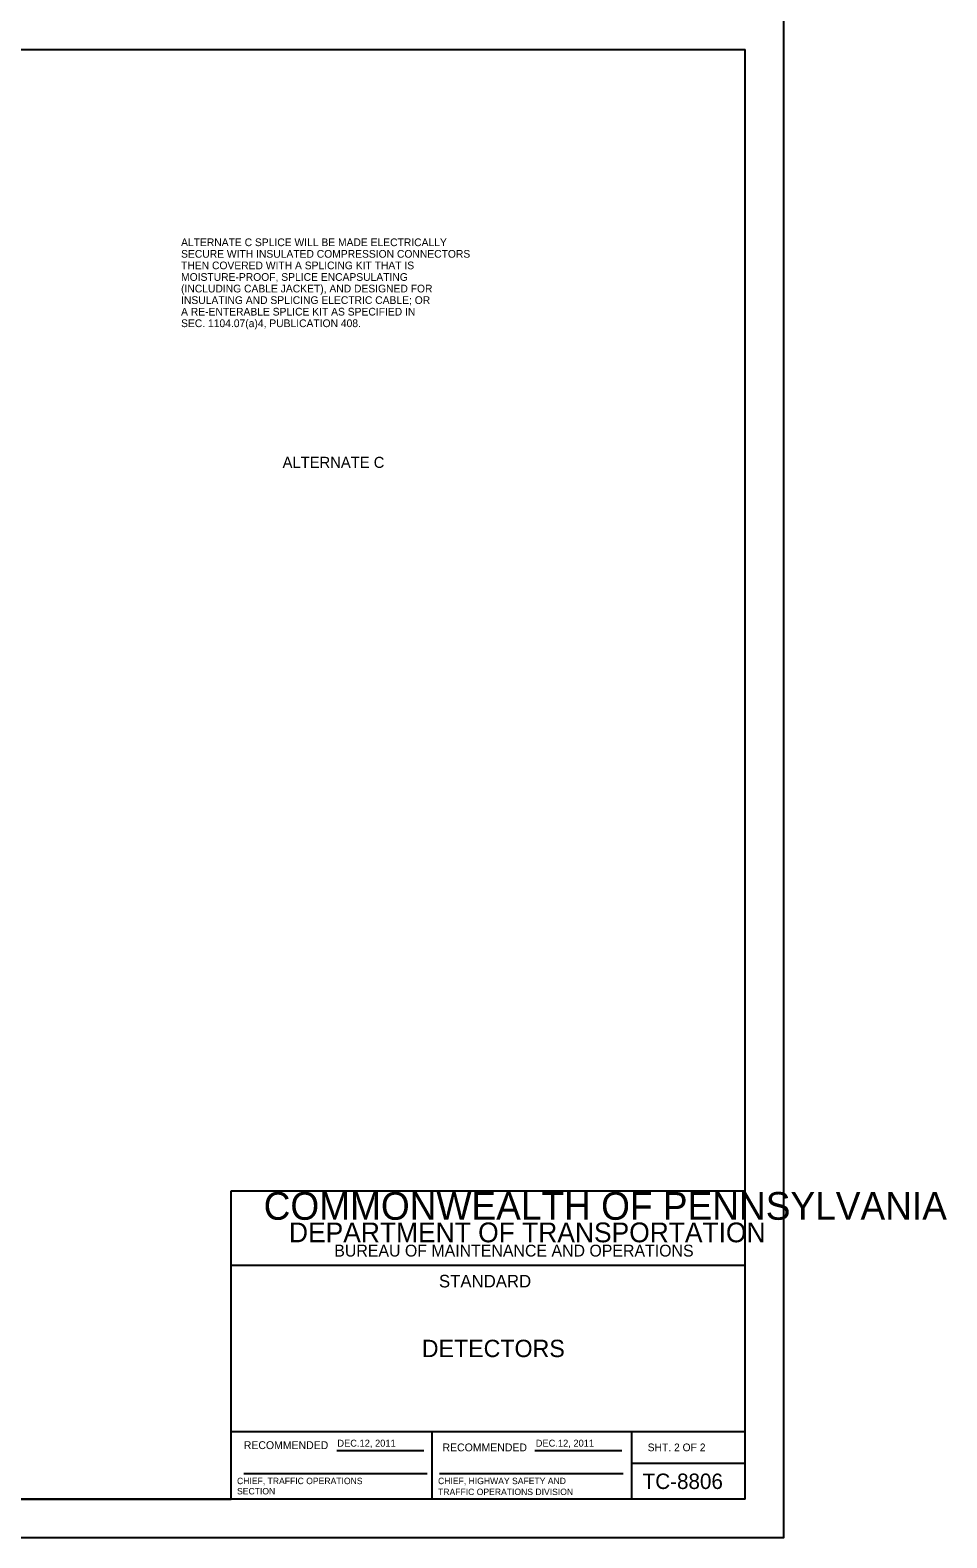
# Model space of a CAD drawing. Extents: x 2709 to 3899, y 22 to 1210.
# Drawn here: x 3257 to 3613, y 22 to 609 of the extents above; entities that cross this region are included whole.
import ezdxf

# ---------------------------------------------------------------- set-up
doc = ezdxf.new("R2010")
doc.units = 0
for name, color, linetype in [('1', 7, 'Continuous'), ('2', 7, 'Continuous'), ('4', 7, 'Continuous'), ('Default', 7, 'Continuous'), ('PLT-BNDY', 7, 'Continuous')]:
    doc.layers.add(name, color=color, linetype=linetype)

msp = doc.modelspace()

# ---------------------------------------------------------------- linework, layer by layer
at = {"layer": '1'}
for p, q in [((2748.86, 601.17), (3534.86, 601.17)), ((3534.86, 37.17), (3534.86, 601.17)), ((3334.86, 37.17), (3334.86, 157.17)), ((3334.86, 157.17), (3534.86, 157.17)), ((3534.86, 128.17), (3334.86, 128.17)), ((3334.86, 63.55), (3534.86, 63.55)), ((3412.86, 63.55), (3412.86, 37.17)), ((3490.73, 37.17), (3490.73, 63.55)), ((3375.9, 56.2), (3409.82, 56.2)), ((3452.99, 56.2), (3486.91, 56.2)), ((3339.74, 47.21), (3411.07, 47.21)), ((3415.95, 47.21), (3487.41, 47.21)), ((3490.73, 51.17), (3534.86, 51.17)), ((3534.86, 37.17), (2748.86, 37.17)), ((2748.86, 37.17), (3334.86, 37.17))]:
    msp.add_line(p, q, dxfattribs=at)
at = {"layer": 'PLT-BNDY'}
msp.add_lwpolyline([(2708.86, 616.17), (3549.86, 616.17), (3549.86, 22.17), (2708.86, 22.17)], close=True, dxfattribs=at)

# ---------------------------------------------------------------- texts
at = {"layer": '1'}
for s, height, p in [('COMMONWEALTH OF PENNSYLVANIA', 10.7828, (3347.45, 145.9)), ('DEPARTMENT OF TRANSPORTATION', 7.6837, (3357.31, 137.15)), ('BUREAU OF MAINTENANCE AND OPERATIONS', 4.6253, (3374.95, 131.59)), ('DETECTORS', 6.75, (3409.01, 92.48)), ('RECOMMENDED', 3.0516, (3339.73, 56.7)), ('RECOMMENDED', 3.0516, (3417.08, 55.82)), ('SHT. 2 OF 2', 3, (3496.94, 55.86)), ('TC-8806', 6, (3495, 41.17))]:
    msp.add_text(s, height=height, dxfattribs=at).set_placement(p)
at = {"layer": '2'}
for s, height, p in [('ALTERNATE C SPLICE WILL BE MADE ELECTRICALLY', 3, (3315.31, 524.65)), ('SECURE WITH INSULATED COMPRESSION CONNECTORS', 3, (3315.31, 520.15)), ('THEN COVERED WITH A SPLICING KIT THAT IS', 3, (3315.31, 515.65)), ('MOISTURE-PROOF, SPLICE ENCAPSULATING', 3, (3315.31, 511.15)), ('(INCLUDING CABLE JACKET), AND DESIGNED FOR', 3, (3315.31, 506.65)), ('INSULATING AND SPLICING ELECTRIC CABLE; OR', 3, (3315.31, 502.15)), ('A RE-ENTERABLE SPLICE KIT AS SPECIFIED IN', 3, (3315.31, 497.65)), ('SEC. 1104.07(a)4, PUBLICATION 408.', 3, (3315.31, 493.15)), ('ALTERNATE C', 4.3, (3354.83, 438.39)), ('DEC.12, 2011', 2.7032, (3376.15, 57.64))]:
    msp.add_text(s, height=height, dxfattribs=at).set_placement(p)
msp.add_text('DEC.12, 2011', height=2.7032, rotation=360, dxfattribs=at).set_placement((3453.37, 57.64))
at = {"layer": '4'}
msp.add_text('STANDARD', height=4.881, rotation=360, dxfattribs=at).set_placement((3415.69, 119.59))
at = {"layer": 'Default'}
for s, p in [('SECTION', (3337.1, 39.06)), ('CHIEF, TRAFFIC OPERATIONS', (3337.1, 43.06)), ('TRAFFIC OPERATIONS DIVISION', (3415.35, 38.81)), ('CHIEF, HIGHWAY SAFETY AND', (3415.35, 43.06))]:
    msp.add_text(s, height=2.5, dxfattribs=at).set_placement(p)

doc.saveas('drawing.dxf')
